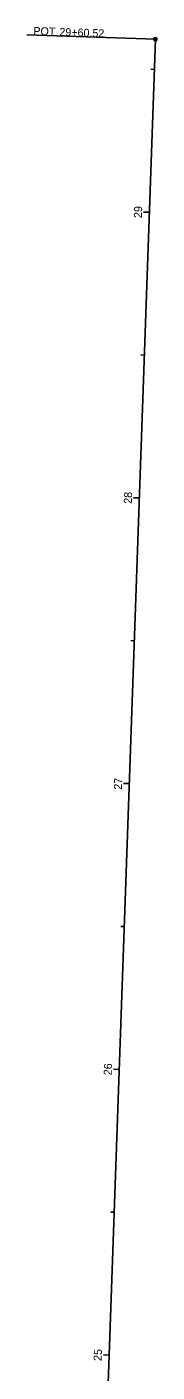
# Model space of a CAD drawing. Extents: x 1471653 to 1473622, y 385397 to 387214.
# Drawn here: x 1472632.6 to 1472678.2, y 386743.6 to 387214.1 of the extents above; entities that cross this region are included whole.
import ezdxf

# ---------------------------------------------------------------- set-up
doc = ezdxf.new("R2010")
doc.units = 0
for name, color, linetype in [('Default', 7, 'Continuous'), ('DT_P_Graded_Shoulder', 7, 'Continuous'), ('GE_X_Alignment', 7, 'Continuous'), ('PV_P_Curb', 7, 'Continuous'), ('PV_P_EOP', 7, 'Continuous')]:
    doc.layers.add(name, color=color, linetype=linetype)

msp = doc.modelspace()

# ---------------------------------------------------------------- linework, layer by layer
at = {"layer": 'Default'}
for centre in [(1472677.6, 387209.74), (1472677.6, 387209.74), (1472677.6, 387209.74), (1472675.47, 387149.26), (1472671.95, 387049.33), (1472668.43, 386949.39), (1472664.91, 386849.45), (1472661.39, 386749.51), (1472661.39, 386749.51)]:
    msp.add_circle(centre, 0.0000833, dxfattribs=at)
at = {"layer": 'DT_P_Graded_Shoulder'}
for p, q in [((1472677.6, 387209.74), (1472632.63, 387211.33)), ((1472675.47, 387149.26), (1472674.27, 387149.31)), ((1472671.95, 387049.33), (1472670.75, 387049.37)), ((1472668.43, 386949.39), (1472667.23, 386949.43)), ((1472664.91, 386849.45), (1472663.71, 386849.49)), ((1472661.39, 386749.51), (1472659.39, 386749.58))]:
    msp.add_line(p, q, dxfattribs=at)
msp.add_circle((1472677.6, 387209.74), 0.6, dxfattribs=at)
at = {"layer": 'GE_X_Alignment'}
for p, q in [((1472677.6, 387209.74), (1472632.63, 387211.33)), ((1472661.39, 386749.51), (1472660.19, 386749.55))]:
    msp.add_line(p, q, dxfattribs=at)
msp.add_circle((1472677.6, 387209.74), 0.6, dxfattribs=at)
at = {"layer": 'PV_P_Curb'}
msp.add_line((1472643.78, 386249.82), (1472677.6, 387209.74), dxfattribs=at)
at = {"layer": 'PV_P_EOP'}
for p, q in [((1472677.6, 387209.74), (1472632.63, 387211.33)), ((1472677.23, 387199.23), (1472676.03, 387199.27)), ((1472675.47, 387149.26), (1472673.47, 387149.33)), ((1472673.71, 387099.29), (1472672.51, 387099.34)), ((1472671.95, 387049.33), (1472669.95, 387049.4)), ((1472670.19, 386999.36), (1472668.99, 386999.4)), ((1472668.43, 386949.39), (1472666.43, 386949.46)), ((1472666.67, 386899.42), (1472665.47, 386899.46)), ((1472664.91, 386849.45), (1472662.91, 386849.52)), ((1472663.15, 386799.48), (1472661.95, 386799.52)), ((1472661.39, 386749.51), (1472659.39, 386749.58))]:
    msp.add_line(p, q, dxfattribs=at)
msp.add_circle((1472677.6, 387209.74), 0.6, dxfattribs=at)

# ---------------------------------------------------------------- texts
at = {"layer": 'DT_P_Graded_Shoulder'}
for s, rotation, p in [('POT', 357.982, (1472634.85, 387211.29)), ('29+60.52', 357.982, (1472643.97, 387210.97)), ('25', 87.982, (1472658.76, 386747.4))]:
    msp.add_text(s, height=2.8, rotation=rotation, dxfattribs=at).set_placement(p)
at = {"layer": 'GE_X_Alignment'}
for s, p in [('POT', (1472634.85, 387211.29)), ('29+60.52', (1472643.97, 387210.97))]:
    msp.add_text(s, height=2.8, rotation=357.982, dxfattribs=at).set_placement(p)
at = {"layer": 'PV_P_EOP'}
for s, rotation, p in [('POT', 357.982, (1472634.85, 387211.29)), ('29+60.52', 357.982, (1472643.97, 387210.97)), ('29', 87.982, (1472672.85, 387147.19)), ('28', 87.982, (1472669.33, 387047.23)), ('27', 87.982, (1472665.85, 386947.22)), ('26', 87.982, (1472662.29, 386847.34)), ('25', 87.982, (1472658.76, 386747.4))]:
    msp.add_text(s, height=2.8, rotation=rotation, dxfattribs=at).set_placement(p)

doc.saveas('drawing.dxf')
